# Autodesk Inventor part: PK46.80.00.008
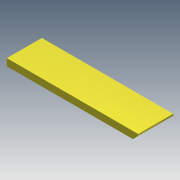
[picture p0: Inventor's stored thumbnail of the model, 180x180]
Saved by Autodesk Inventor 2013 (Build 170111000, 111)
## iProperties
Shininess: 64.0
Length Units: 11269
Angle Units: 11279
Time Units: 11290
Mass Units: 11283
Length Display Precision: 3
Angle Display Precision: 2
Compacted: True
Part Number: PK46.80.00.008
Document SubType Name: Modeling
Created: 2005-01
Material: Steel, Mild
Designer: SAlex
Manufacturer: Standard
Standards Organization: Custom
Density: 7.86 g/cm^3
Mass: 2972.97 g
Surface Area: 594.536 cm^2
Volume: 378.24 cm^3
Density: 0.0
Volumn: 0.0
Area: 0.0
PropertySet Name: Model Information
Control State: 0
Master: False
Checked Out: False
Checked Out Date: 2008-10-15
Last Check In Date: 2008-10-15
Author: SAlex
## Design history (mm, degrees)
sketch "Sketch1"
  geometry: L1 (0, 0)-(300, 0); L2 (300, 0)-(300, 80); L3 (300, 80)-(0, 80); L4 (0, 80)-(0, 0)
  constraints: 8 end point, 2 parallel, 1 horizontal, 1 perpendicular, 1 other
  dimensions: "d0" = 300 distance of L1.start L1.end; "d1" = 80 distance of L3.end L1.start
extrude "Extrusion1" new body sketch "Sketch1" distance "d2" = 16; taper "d3" = 0 deg
chamfer "Chamfer1" distance "d4" = 12; stored, may be unused: second distance "d5" = 2, angle "d6" = 45 deg
body "Solid1"
